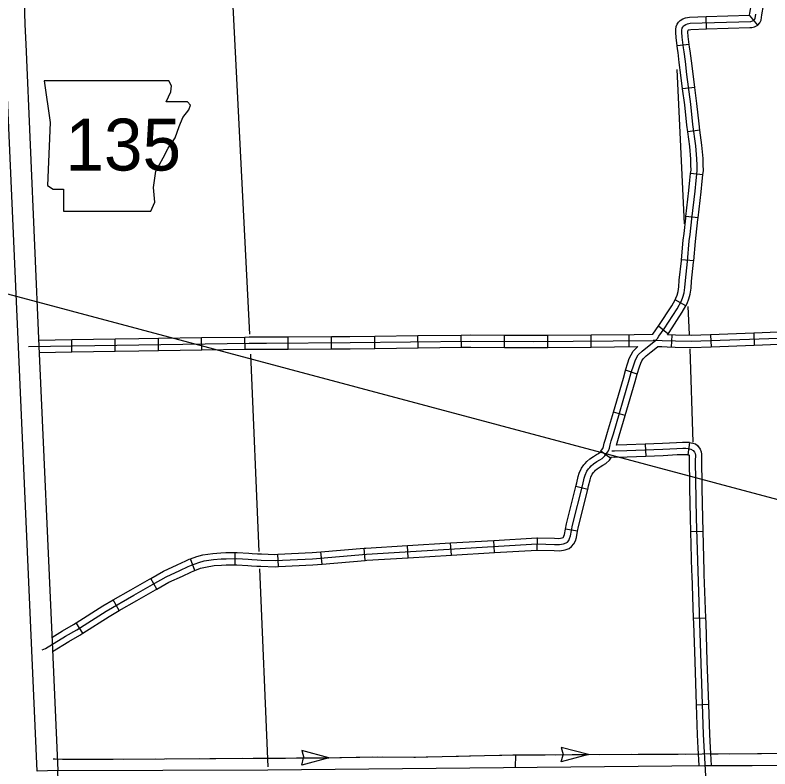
# Model space of a CAD drawing. Extents: x -5566 to 1759129, y -3726 to 731467.
# Drawn here: x -4997.6 to -4927.6, y 310.6 to 380.4 of the extents above; entities that cross this region are included whole.
import ezdxf

# ---------------------------------------------------------------- set-up
doc = ezdxf.new("R2010")
doc.units = 0
doc.layers.add('Default', color=7, linetype='Continuous')

msp = doc.modelspace()

# ---------------------------------------------------------------- linework, layer by layer
at = {"layer": 'Default'}
for p, q in [((-4933.486, 379.153), (-4933.52, 380.292)), ((-4928.749, 379.504), (-4929.512, 380.412)), ((-4935.084, 377.714), (-4936.215, 377.573)), ((-4934.572, 373.74), (-4935.702, 373.594)), ((-4934.102, 369.764), (-4935.231, 369.606)), ((-5045.078, 367.089), (-4814.177, 305.513)), ((-4933.83, 365.641), (-4934.964, 365.751)), ((-4934.269, 361.644), (-4935.4, 361.777)), ((-4934.677, 357.672), (-4935.811, 357.773)), ((-4935.405, 353.516), (-4936.401, 354.069)), ((-4937.073, 350.899), (-4937.942, 351.635)), ((-4984.275, 349.359), (-4984.291, 350.498)), ((-4980.265, 349.418), (-4980.282, 350.557)), ((-4976.256, 349.477), (-4976.273, 350.616)), ((-4972.251, 349.499), (-4972.258, 350.638)), ((-4968.242, 349.522), (-4968.249, 350.662)), ((-4964.229, 349.561), (-4964.243, 350.7)), ((-4960.219, 349.611), (-4960.233, 350.75)), ((-4956.21, 349.661), (-4956.224, 350.8)), ((-4952.21, 349.656), (-4952.204, 350.795)), ((-4948.193, 349.654), (-4948.202, 350.793)), ((-4944.183, 349.688), (-4944.193, 350.827)), ((-4940.654, 349.717), (-4940.664, 350.856)), ((-4936.719, 350.8), (-4936.764, 349.661)), ((-4933.116, 350.824), (-4933.074, 349.685)), ((-4929.109, 350.972), (-4929.067, 349.833)), ((-4992.292, 349.232), (-4992.311, 350.371)), ((-4988.283, 349.297), (-4988.302, 350.436)), ((-4939.918, 347.182), (-4941.001, 347.536)), ((-4941.023, 343.347), (-4942.117, 343.666)), ((-4939.164, 340.698), (-4939.12, 339.56)), ((-4935.057, 340.832), (-4935.215, 339.7)), ((-4942.356, 339.377), (-4943.273, 340.053)), ((-4944.501, 336.476), (-4945.606, 336.755)), ((-4945.443, 332.617), (-4946.563, 332.824)), ((-4934.976, 332.592), (-4933.837, 332.623)), ((-4953.133, 330.642), (-4953.201, 331.779)), ((-4949.179, 330.878), (-4949.15, 332.017)), ((-4965.127, 329.919), (-4965.222, 331.054)), ((-4961.138, 330.162), (-4961.206, 331.299)), ((-4957.136, 330.402), (-4957.204, 331.539)), ((-4977.173, 329.517), (-4977.182, 330.656)), ((-4973.144, 329.351), (-4973.202, 330.488)), ((-4969.123, 329.585), (-4969.218, 330.72)), ((-4980.921, 328.994), (-4981.317, 330.062)), ((-4984.429, 327.263), (-4984.995, 328.252)), ((-4987.907, 325.27), (-4988.475, 326.258)), ((-4934.722, 324.572), (-4933.584, 324.613)), ((-4991.297, 323.176), (-4991.907, 324.138)), ((-4934.45, 316.558), (-4933.311, 316.597)), ((-4971.007, 312.309), (-4970.822, 311.64)), ((-4968.487, 311.642), (-4971.007, 312.309)), ((-4944.432, 311.945), (-4946.953, 312.606)), ((-4946.953, 312.606), (-4946.77, 311.937)), ((-4968.487, 311.642), (-4971.002, 310.959)), ((-4971.002, 310.959), (-4970.828, 311.631)), ((-4944.432, 311.945), (-4946.946, 311.257)), ((-4946.946, 311.257), (-4946.77, 311.928))]:
    msp.add_line(p, q, dxfattribs=at)
for points in [[(-4993.615, 310.476), (-4995.511, 310.392), (-4996.003, 321.585), (-4997.259, 349.695), (-4998.481, 377.677), (-4998.548, 379.506), (-4998.756, 386.137), (-4999.305, 409.605), (-4999.405, 414.253)], [(-4997.507, 414.294), (-4997.407, 409.647), (-4996.858, 386.189), (-4996.65, 379.571), (-4996.584, 377.753), (-4995.362, 349.779), (-4994.106, 321.669), (-4993.615, 310.476)], [(-4977.818, 389.769), (-4975.835, 350.875)], [(-4929.512, 380.412), (-4929.509, 380.412), (-4929.488, 380.615), (-4929.33, 381.476), (-4929.283, 381.902), (-4929.247, 382.427), (-4929.178, 382.947), (-4929.09, 383.561)], [(-4929.478, 379.273), (-4929.291, 379.279), (-4929.028, 379.357), (-4928.749, 379.504), (-4928.559, 379.719), (-4928.429, 379.949), (-4928.385, 380.217), (-4928.36, 380.452), (-4928.202, 381.31), (-4928.148, 381.8), (-4928.113, 382.313), (-4928.049, 382.791), (-4927.962, 383.4)], [(-4940.467, 347.337), (-4940.239, 348.036), (-4940.114, 348.415), (-4939.984, 348.689), (-4939.827, 348.951), (-4939.461, 349.31), (-4938.971, 349.698), (-4938.365, 350.176), (-4938.203, 350.301), (-4938.046, 350.487), (-4937.9, 350.689), (-4937.425, 351.36), (-4936.224, 353.213), (-4935.807, 353.966), (-4935.679, 354.312), (-4935.574, 354.716), (-4935.493, 355.201), (-4935.445, 355.84), (-4935.255, 357.603), (-4935.085, 359.512), (-4935.006, 360.123), (-4934.852, 361.566), (-4934.551, 364.133), (-4934.456, 365.097), (-4934.397, 365.7), (-4934.353, 366.053), (-4934.367, 366.546), (-4934.375, 367.128), (-4934.478, 368.335), (-4934.752, 370.294), (-4934.944, 372.174), (-4935.299, 374.93), (-4935.446, 376.12), (-4935.565, 377.036), (-4935.618, 377.392), (-4935.744, 378.402), (-4935.778, 378.854), (-4935.776, 379.036), (-4935.744, 379.219), (-4935.698, 379.325), (-4935.645, 379.405), (-4935.572, 379.472), (-4935.412, 379.571), (-4935.266, 379.631), (-4935.001, 379.677), (-4929.382, 379.846), (-4929.244, 379.887), (-4929.107, 379.96), (-4929.025, 380.051), (-4928.975, 380.141), (-4928.949, 380.294), (-4928.924, 380.533)], [(-4936.215, 377.573), (-4936.311, 378.346), (-4936.347, 378.835), (-4936.345, 379.087), (-4936.294, 379.384), (-4936.2, 379.6), (-4936.08, 379.779), (-4935.917, 379.927), (-4935.673, 380.08), (-4935.425, 380.181), (-4935.059, 380.246), (-4933.52, 380.292)], [(-4933.52, 380.292), (-4929.512, 380.412)], [(-4935.084, 377.714), (-4935.177, 378.458), (-4935.208, 378.872), (-4935.207, 378.985), (-4935.198, 379.033), (-4935.152, 379.062), (-4935.107, 379.081), (-4934.943, 379.109), (-4933.486, 379.153)], [(-4933.486, 379.153), (-4929.478, 379.273)], [(-4935.702, 373.594), (-4935.865, 374.859), (-4936.011, 376.048), (-4936.129, 376.957), (-4936.183, 377.315), (-4936.215, 377.573)], [(-4934.572, 373.74), (-4934.734, 375.002), (-4934.88, 376.191), (-4935.001, 377.115), (-4935.054, 377.47), (-4935.084, 377.714)], [(-4936.242, 375.397), (-4935.576, 361.111)], [(-4935.231, 369.606), (-4935.317, 370.225), (-4935.51, 372.108), (-4935.702, 373.594)], [(-4934.102, 369.764), (-4934.186, 370.362), (-4934.378, 372.239), (-4934.572, 373.74)], [(-4934.964, 365.751), (-4934.963, 365.762), (-4934.923, 366.08), (-4934.937, 366.534), (-4934.944, 367.1), (-4935.044, 368.271), (-4935.231, 369.606)], [(-4933.831, 365.637), (-4933.782, 366.026), (-4933.798, 366.558), (-4933.805, 367.155), (-4933.912, 368.399), (-4934.102, 369.764)], [(-4935.4, 361.777), (-4935.118, 364.194), (-4935.022, 365.153), (-4934.964, 365.751)], [(-4934.269, 361.644), (-4933.985, 364.071), (-4933.889, 365.041), (-4933.83, 365.641)], [(-4935.811, 357.773), (-4935.651, 359.574), (-4935.571, 360.19), (-4935.418, 361.63), (-4935.4, 361.777)], [(-4934.677, 357.672), (-4934.518, 359.45), (-4934.44, 360.057), (-4934.286, 361.503), (-4934.269, 361.644)], [(-4936.401, 354.069), (-4936.326, 354.204), (-4936.223, 354.483), (-4936.132, 354.835), (-4936.059, 355.27), (-4936.012, 355.892), (-4935.821, 357.659), (-4935.811, 357.773)], [(-4935.405, 353.516), (-4935.288, 353.728), (-4935.135, 354.141), (-4935.016, 354.598), (-4934.927, 355.133), (-4934.877, 355.788), (-4934.688, 357.548), (-4934.677, 357.672)], [(-4938.466, 350.875), (-4937.897, 351.68), (-4936.713, 353.506), (-4936.401, 354.069)], [(-4937.113, 350.815), (-4936.953, 351.041), (-4935.736, 352.92), (-4935.405, 353.516)], [(-4935.218, 353.451), (-4935.097, 350.847)], [(-4905.045, 351.258), (-4914.984, 350.928), (-4918.794, 350.756), (-4926.807, 350.487), (-4934.899, 350.188), (-4936.372, 350.216), (-4937.605, 350.264), (-4938.203, 350.301), (-4938.43, 350.305)], [(-4988.302, 350.436), (-4986.102, 350.472), (-4984.291, 350.498)], [(-4984.291, 350.498), (-4980.282, 350.557)], [(-4980.282, 350.557), (-4976.273, 350.616)], [(-4976.273, 350.616), (-4975.871, 350.622), (-4974.282, 350.626), (-4972.258, 350.638)], [(-4972.258, 350.638), (-4968.249, 350.662)], [(-4968.249, 350.662), (-4966.534, 350.672), (-4964.243, 350.7)], [(-4964.243, 350.7), (-4960.233, 350.75)], [(-4960.233, 350.75), (-4956.224, 350.8)], [(-4956.224, 350.8), (-4955.338, 350.811), (-4952.204, 350.795)], [(-4952.204, 350.795), (-4949.566, 350.782), (-4948.202, 350.793)], [(-4948.202, 350.793), (-4944.193, 350.827)], [(-4944.193, 350.827), (-4940.183, 350.86)], [(-4940.183, 350.86), (-4938.466, 350.875)], [(-4933.116, 350.824), (-4934.904, 350.757), (-4936.355, 350.785), (-4937.113, 350.815)], [(-4929.109, 350.972), (-4933.116, 350.824)], [(-4925.099, 351.114), (-4926.827, 351.056), (-4929.109, 350.972)], [(-4996.311, 349.737), (-4986.093, 349.902), (-4975.866, 350.052), (-4974.28, 350.056), (-4966.528, 350.102), (-4955.336, 350.241), (-4949.565, 350.212), (-4938.43, 350.305)], [(-4995.386, 350.321), (-4992.311, 350.371)], [(-4992.311, 350.371), (-4988.302, 350.436)], [(-4929.067, 349.833), (-4933.074, 349.685)], [(-4925.061, 349.976), (-4926.787, 349.918), (-4929.067, 349.833)], [(-4995.336, 349.183), (-4992.292, 349.232)], [(-4992.292, 349.232), (-4988.283, 349.297)], [(-4988.283, 349.297), (-4986.084, 349.333), (-4984.275, 349.359)], [(-4984.275, 349.359), (-4980.265, 349.418)], [(-4980.265, 349.418), (-4976.256, 349.477)], [(-4976.256, 349.477), (-4975.861, 349.482), (-4974.277, 349.487), (-4972.251, 349.499)], [(-4972.251, 349.499), (-4968.242, 349.522)], [(-4968.242, 349.522), (-4966.523, 349.533), (-4964.229, 349.561)], [(-4964.229, 349.561), (-4960.219, 349.611)], [(-4960.219, 349.611), (-4956.21, 349.661)], [(-4956.21, 349.661), (-4955.334, 349.672), (-4952.21, 349.656)], [(-4952.21, 349.656), (-4949.564, 349.643), (-4948.193, 349.654)], [(-4948.193, 349.654), (-4944.183, 349.688)], [(-4944.183, 349.688), (-4939.853, 349.724)], [(-4941.001, 347.536), (-4940.78, 348.213), (-4940.644, 348.627), (-4940.486, 348.959), (-4940.278, 349.306), (-4939.853, 349.724)], [(-4939.918, 347.182), (-4939.697, 347.859), (-4939.584, 348.203), (-4939.481, 348.42), (-4939.376, 348.596), (-4939.084, 348.883), (-4938.618, 349.251), (-4938.024, 349.719)], [(-4937.125, 349.676), (-4937.633, 349.696), (-4938.024, 349.719)], [(-4933.074, 349.685), (-4934.894, 349.618), (-4936.389, 349.647), (-4937.125, 349.676)], [(-4935.046, 349.515), (-4934.767, 340.871)], [(-4975.748, 349.021), (-4974.978, 330.751)], [(-4995.055, 321.627), (-4994.737, 321.757), (-4992.882, 322.905), (-4991.854, 323.498), (-4989.14, 325.218), (-4986.569, 326.696), (-4984.826, 327.692), (-4983.564, 328.415), (-4982.293, 328.996), (-4981.511, 329.363), (-4981.207, 329.496), (-4980.54, 329.743), (-4980.044, 329.869), (-4979.188, 330.01), (-4978.477, 330.056), (-4978.02, 330.08), (-4977.012, 330.088), (-4975.955, 330.033), (-4975.624, 330.003), (-4975.139, 329.974), (-4974.756, 329.949), (-4973.476, 329.904), (-4970, 330.083), (-4965.009, 330.501), (-4949.199, 331.449), (-4947.593, 331.407), (-4947.129, 331.395), (-4946.743, 331.449), (-4946.499, 331.538), (-4946.386, 331.627), (-4946.261, 331.77), (-4946.178, 331.948), (-4946.1, 332.192), (-4945.916, 333.192), (-4944.967, 336.958), (-4944.819, 337.541), (-4944.741, 337.821), (-4944.59, 338.182), (-4944.42, 338.416), (-4944.316, 338.538), (-4944.185, 338.687), (-4943.977, 338.86), (-4943.65, 339.074), (-4943.388, 339.235), (-4943.162, 339.365), (-4942.901, 339.597), (-4942.651, 339.937), (-4942.574, 340.073), (-4942.496, 340.329), (-4942.425, 340.633), (-4942.318, 340.996), (-4942.116, 341.632), (-4940.65, 346.663), (-4940.467, 347.337)], [(-4942.117, 343.666), (-4941.198, 346.818), (-4941.013, 347.5), (-4941.001, 347.536)], [(-4941.023, 343.347), (-4940.102, 346.509), (-4939.921, 347.173), (-4939.918, 347.182)], [(-4943.273, 340.053), (-4943.13, 340.247), (-4943.101, 340.299), (-4943.047, 340.477), (-4942.976, 340.779), (-4942.863, 341.162), (-4942.661, 341.798), (-4942.117, 343.666)], [(-4941.839, 340.606), (-4941.773, 340.829), (-4941.571, 341.466), (-4941.023, 343.347)], [(-4939.164, 340.698), (-4940.879, 340.631), (-4941.839, 340.606)], [(-4935.057, 340.832), (-4935.093, 340.837), (-4935.392, 340.843), (-4935.704, 340.846), (-4936.273, 340.829), (-4937.563, 340.761), (-4939.164, 340.698)], [(-4935.057, 340.832), (-4934.749, 340.789), (-4934.517, 340.713), (-4934.328, 340.557), (-4934.083, 340.227), (-4934, 339.967), (-4933.954, 339.76), (-4933.94, 339.489), (-4933.922, 336.627)], [(-4945.606, 336.755), (-4945.52, 337.098), (-4945.369, 337.687), (-4945.281, 338.008), (-4945.09, 338.463), (-4944.869, 338.767), (-4944.747, 338.911), (-4944.583, 339.097), (-4944.316, 339.319), (-4943.955, 339.555), (-4943.68, 339.724), (-4943.497, 339.83), (-4943.324, 339.984), (-4943.273, 340.053)], [(-4935.136, 340.268), (-4935.139, 340.268), (-4935.4, 340.274), (-4935.698, 340.277), (-4936.249, 340.26), (-4937.537, 340.192), (-4940.861, 340.062), (-4942.032, 340.032), (-4942.258, 340.044)], [(-4935.136, 340.268), (-4934.932, 340.239), (-4934.712, 340.118), (-4934.597, 339.963), (-4934.55, 339.818), (-4934.52, 339.683), (-4934.512, 339.514), (-4934.542, 339.298), (-4934.537, 339.124), (-4934.44, 333.834), (-4934.306, 328.927), (-4934.137, 324.131), (-4933.786, 313.783), (-4933.595, 309.971)], [(-4944.501, 336.476), (-4944.415, 336.818), (-4944.268, 337.395), (-4944.202, 337.634), (-4944.09, 337.9), (-4943.972, 338.064), (-4943.885, 338.166), (-4943.787, 338.277), (-4943.638, 338.401), (-4943.345, 338.593), (-4943.097, 338.745), (-4942.827, 338.901), (-4942.478, 339.211), (-4942.284, 339.475)], [(-4939.12, 339.56), (-4940.842, 339.492), (-4942.04, 339.462), (-4942.284, 339.475)], [(-4935.215, 339.7), (-4935.409, 339.704), (-4935.692, 339.707), (-4936.225, 339.691), (-4937.511, 339.623), (-4939.12, 339.56)], [(-4935.215, 339.7), (-4935.115, 339.69), (-4935.106, 339.685), (-4935.101, 339.67), (-4935.087, 339.607), (-4935.083, 339.539), (-4935.061, 336.606)], [(-4946.563, 332.824), (-4946.473, 333.313), (-4945.606, 336.755)], [(-4945.443, 332.617), (-4945.359, 333.071), (-4944.501, 336.476)], [(-4935.061, 336.606), (-4935.009, 333.821), (-4934.976, 332.592)], [(-4933.922, 336.627), (-4933.87, 333.847), (-4933.837, 332.623)], [(-4949.179, 330.878), (-4947.608, 330.838), (-4947.097, 330.825), (-4946.604, 330.893), (-4946.217, 331.034), (-4945.992, 331.213), (-4945.779, 331.456), (-4945.646, 331.741), (-4945.547, 332.054), (-4945.443, 332.617)], [(-4949.15, 332.017), (-4947.579, 331.976), (-4947.161, 331.966), (-4946.881, 332.004), (-4946.78, 332.041), (-4946.78, 332.042), (-4946.743, 332.084), (-4946.71, 332.156), (-4946.654, 332.331), (-4946.563, 332.824)], [(-4934.976, 332.592), (-4934.876, 328.909), (-4934.864, 328.58)], [(-4933.837, 332.623), (-4933.737, 328.945), (-4933.726, 328.62)], [(-4957.204, 331.539), (-4953.201, 331.779)], [(-4953.201, 331.779), (-4949.209, 332.019), (-4949.15, 332.017)], [(-4969.218, 330.72), (-4965.222, 331.054)], [(-4965.222, 331.054), (-4965.049, 331.069), (-4961.206, 331.299)], [(-4961.206, 331.299), (-4957.204, 331.539)], [(-4953.133, 330.642), (-4949.189, 330.879), (-4949.179, 330.878)], [(-4981.317, 330.062), (-4980.71, 330.287), (-4980.161, 330.427), (-4979.253, 330.577), (-4978.51, 330.625), (-4978.037, 330.649), (-4977.182, 330.656)], [(-4977.182, 330.656), (-4977, 330.657), (-4975.915, 330.601), (-4975.581, 330.571), (-4975.103, 330.542), (-4974.728, 330.518), (-4973.481, 330.474), (-4973.202, 330.488)], [(-4973.202, 330.488), (-4970.039, 330.651), (-4969.218, 330.72)], [(-4965.127, 329.919), (-4964.968, 329.933), (-4961.138, 330.162)], [(-4961.138, 330.162), (-4957.136, 330.402)], [(-4957.136, 330.402), (-4953.133, 330.642)], [(-4984.995, 328.252), (-4983.824, 328.922), (-4982.532, 329.513), (-4981.746, 329.882), (-4981.419, 330.024), (-4981.317, 330.062)], [(-4980.921, 328.994), (-4980.37, 329.198), (-4979.927, 329.311), (-4979.123, 329.444), (-4978.444, 329.488), (-4978.003, 329.51), (-4977.173, 329.517)], [(-4977.173, 329.517), (-4977.025, 329.518), (-4975.995, 329.465), (-4975.667, 329.435), (-4975.175, 329.405), (-4974.785, 329.38), (-4973.471, 329.334), (-4973.144, 329.351)], [(-4973.144, 329.351), (-4969.962, 329.515), (-4969.123, 329.585)], [(-4969.123, 329.585), (-4965.127, 329.919)], [(-4984.429, 327.263), (-4983.303, 327.908), (-4982.053, 328.479), (-4981.277, 328.844), (-4980.994, 328.967), (-4980.921, 328.994)], [(-4974.91, 329.135), (-4974.137, 310.811)], [(-4988.475, 326.258), (-4986.853, 327.19), (-4985.109, 328.186), (-4984.995, 328.252)], [(-4934.864, 328.58), (-4934.722, 324.572)], [(-4933.726, 328.62), (-4933.584, 324.613)], [(-4987.907, 325.27), (-4986.286, 326.201), (-4984.543, 327.198), (-4984.429, 327.263)], [(-4991.907, 324.138), (-4989.434, 325.706), (-4988.475, 326.258)], [(-4991.297, 323.176), (-4988.845, 324.731), (-4987.907, 325.27)], [(-4934.722, 324.572), (-4934.706, 324.111), (-4934.586, 320.566)], [(-4933.584, 324.613), (-4933.568, 324.151), (-4933.447, 320.604)], [(-4994.156, 322.787), (-4993.174, 323.394), (-4992.148, 323.985), (-4991.907, 324.138)], [(-4994.098, 321.483), (-4992.59, 322.416), (-4991.559, 323.01), (-4991.297, 323.176)], [(-4934.586, 320.566), (-4934.45, 316.558)], [(-4933.447, 320.604), (-4933.311, 316.597)], [(-4934.45, 316.558), (-4934.355, 313.76), (-4934.294, 312.543)], [(-4933.311, 316.597), (-4933.217, 313.807), (-4933.156, 312.6)], [(-4933.878, 312.005), (-4928.768, 312.031), (-4922.866, 312.057), (-4913.286, 312.382), (-4896.335, 312.67), (-4893.16, 312.698)], [(-4994.048, 311.553), (-4993.84, 311.534), (-4993.187, 311.524), (-4988.47, 311.506), (-4974.21, 311.615), (-4968.99, 311.633), (-4963.942, 311.729), (-4960.622, 311.705), (-4954.054, 311.86), (-4951.296, 311.908), (-4939.813, 311.97), (-4936.122, 311.97), (-4933.878, 312.005)], [(-4935.41, 311.981), (-4934.267, 311.999)], [(-4934.294, 312.543), (-4934.212, 310.914)], [(-4933.156, 312.6), (-4933.072, 310.92)], [(-4933.127, 312.009), (-4932.403, 312.012)], [(-4931.401, 312.017), (-4928.768, 312.031), (-4928.393, 312.032)], [(-4991.542, 311.518), (-4988.535, 311.506)], [(-4987.533, 311.513), (-4984.526, 311.536)], [(-4983.523, 311.544), (-4980.516, 311.567)], [(-4979.514, 311.575), (-4976.506, 311.598)], [(-4975.504, 311.605), (-4974.21, 311.615), (-4972.497, 311.621)], [(-4971.494, 311.625), (-4969.991, 311.63)], [(-4969.991, 311.63), (-4968.99, 311.633), (-4968.487, 311.642)], [(-4967.485, 311.661), (-4964.478, 311.719)], [(-4963.476, 311.725), (-4960.622, 311.705), (-4960.469, 311.708)], [(-4959.466, 311.732), (-4956.46, 311.803)], [(-4955.458, 311.827), (-4954.054, 311.86), (-4952.451, 311.888)], [(-4951.449, 311.906), (-4951.296, 311.908), (-4948.442, 311.924)], [(-4951.198, 311.909), (-4951.209, 310.749)], [(-4947.439, 311.929), (-4945.936, 311.937)], [(-4945.936, 311.937), (-4944.432, 311.945)], [(-4943.429, 311.951), (-4940.422, 311.967)], [(-4939.42, 311.97), (-4936.412, 311.97)], [(-4933.595, 310.92), (-4929.263, 310.92), (-4922.795, 310.955), (-4915.325, 311.089), (-4913.261, 311.108), (-4902.993, 311.328), (-4900.183, 311.446), (-4894.475, 311.466), (-4894.213, 311.471)], [(-4993.533, 308.577), (-4993.615, 310.476), (-4974.148, 310.525), (-4933.595, 310.92)]]:
    msp.add_lwpolyline(points, dxfattribs=at)
msp.add_lwpolyline([(-4994.879, 374.342), (-4994.301, 370.487), (-4994.558, 364.641), (-4994.044, 364.32), (-4993.08, 364.32), (-4993.08, 362.265), (-4984.986, 362.265), (-4984.601, 363.1), (-4984.729, 364.449), (-4984.537, 365.991), (-4983.83, 367.211), (-4983.38, 368.11), (-4982.738, 369.074), (-4982.353, 370.102), (-4982.031, 370.937), (-4981.453, 371.644), (-4981.325, 372.093), (-4981.582, 372.414), (-4983.573, 372.414), (-4983.123, 373.314), (-4983.059, 373.892), (-4983.326, 374.336)], close=True, dxfattribs=at)

# ---------------------------------------------------------------- texts
msp.add_text('135', height=4.8071, dxfattribs=at).set_placement((-4992.909, 366.035))

doc.saveas('drawing.dxf')
